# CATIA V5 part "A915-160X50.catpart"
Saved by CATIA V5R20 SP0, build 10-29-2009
Part number: A915-160X50
Source: Unknown
Property "A": "110.000"
Property "ARTICLENO": "A915-160X50"
Property "BOMINFO": "A915-160X50"
Property "CODE": "A915-160X50"
Property "CREATOR": "CADENAS GmbH"
Property "D": "13.500"
Property "D1": "20.000"
Property "FORM": "A"
Property "L": "50.000"
Property "L1": "25.000"
Property "L2": "0.000"
Property "LINA": "A915-160X50"
Property "NB": "A915-160X50"
Property "NBSYN": "$CODE."
Property "NN": "A915"
Property "NT": "VDI 3357 Wear Plates, steel"
Property "SCREW": "M12x25"
Property "SUPPLIER": "CF"
Property "T": "13.000"
Property "W": "160.000"
Bounding box of the stored display mesh (mm): x 0 to 20, y 0 to 50, z -80 to 80
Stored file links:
  C:\Users\borellobunino\Desktop\3D X SITO CF\A915\GSB_OILLESS_G22501160050\CATIAV5\A915-160X50.catpart
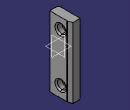
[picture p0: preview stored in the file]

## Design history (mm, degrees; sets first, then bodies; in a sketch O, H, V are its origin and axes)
Body1 "Geometry.1" (main body)
  Solid1 "A915-160X50.catpart": solid without history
